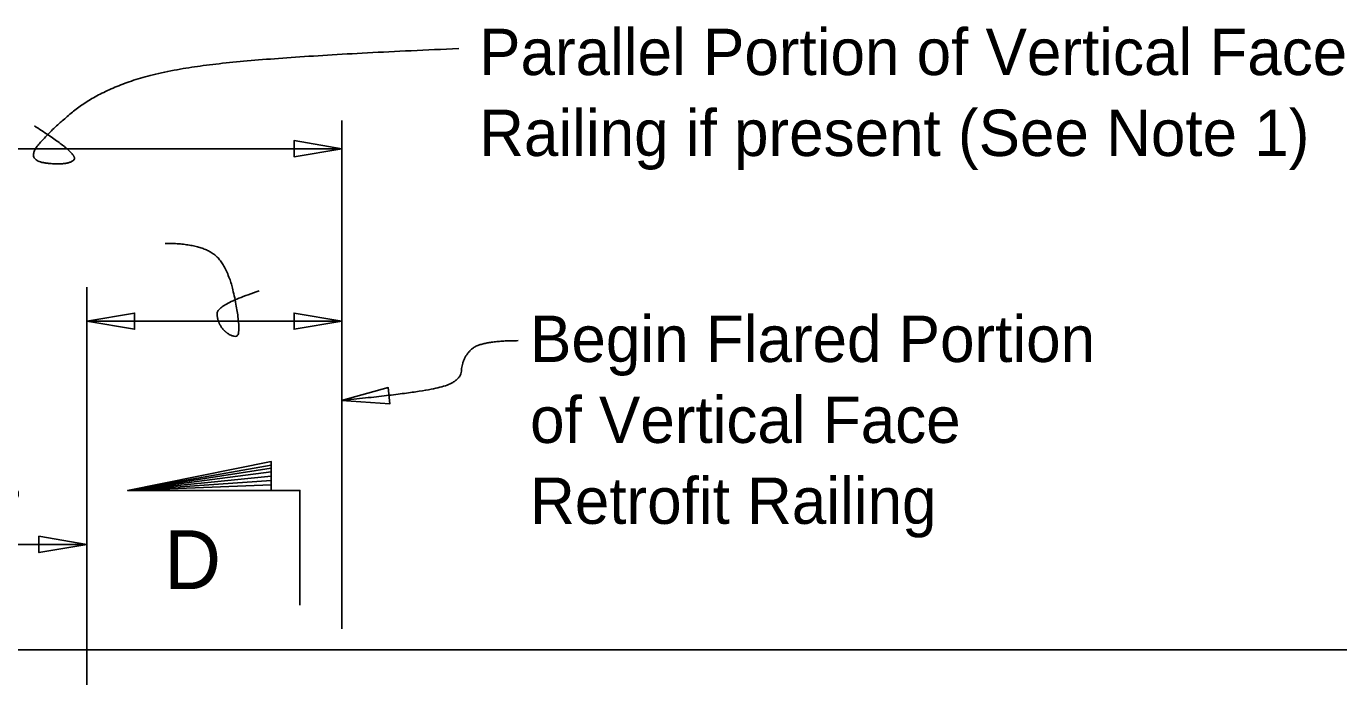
# Model space of a CAD drawing. Extents: x 1.5 to 68.7, y 0 to 31.1.
# Drawn here: x 28.44 to 34.15, y 13.67 to 16.53 of the extents above; entities that cross this region are included whole.
import ezdxf

# ---------------------------------------------------------------- set-up
doc = ezdxf.new("R2010")
doc.units = 0
for name, color, linetype in [('AdhocPoint_dp', 7, 'Continuous'), ('PlotBorder_dp', 7, 'Continuous'), ('SheetBorder_dp', 7, 'Continuous')]:
    doc.layers.add(name, color=color, linetype=linetype)

msp = doc.modelspace()

# ---------------------------------------------------------------- linework, layer by layer
at = {"layer": 'AdhocPoint_dp'}
for p, q in [((29.8106, 13.981), (29.8106, 16.1198)), ((29.8106, 16.0948), (29.8106, 13.9093)), ((28.7009, 13.6663), (28.7009, 15.3961)), ((29.8106, 15.2478), (28.7009, 15.2478)), ((28.878, 14.5119), (29.503, 14.6219)), ((29.503, 14.6085), (28.878, 14.5119)), ((28.878, 14.5119), (29.503, 14.5919)), ((29.503, 14.5735), (28.878, 14.5119)), ((28.878, 14.5119), (29.503, 14.5552)), ((29.503, 14.5352), (28.878, 14.5119))]:
    msp.add_line(p, q, dxfattribs=at)
for points in [[(26.2771, 15.9978), (29.8106, 15.9978)], [(29.628, 14.0119), (29.628, 14.5119), (28.878, 14.5119), (29.503, 14.6369), (29.503, 14.5119)]]:
    msp.add_lwpolyline(points, dxfattribs=at)
for points in [[(29.8106, 15.9978), (29.6024, 16.0331), (29.6024, 15.9626)], [(28.7009, 15.2478), (28.9091, 15.2126), (28.9091, 15.2831)], [(29.8106, 15.2478), (29.6024, 15.2831), (29.6024, 15.2126)], [(29.8085, 14.903), (30.0192, 14.8883), (30.0123, 14.9585)], [(28.7009, 14.2766), (28.4926, 14.3119), (28.4926, 14.2413)]]:
    msp.add_lwpolyline(points, close=True, dxfattribs=at)
for points in [[(30.3185, 16.4334), (29.7625, 16.41), (29.085, 16.3539), (28.7533, 16.2464), (28.5617, 16.0968), (28.4309, 15.9472), (28.6131, 15.9239), (28.6738, 15.9706), (28.4729, 16.0968)], [(29.0412, 15.5861), (29.189, 15.5861), (29.3172, 15.4924), (29.3763, 15.1816), (29.3221, 15.1816), (29.2679, 15.2408), (29.2679, 15.3197), (29.4502, 15.3789)], [(30.5774, 15.1629), (30.4111, 15.1629), (30.3332, 15.0849), (30.328, 14.9809), (30.1253, 14.9341), (29.8084, 14.903)], [(27.8361, 14.5528), (28.0726, 14.5528), (28.3289, 14.5528), (28.4472, 14.4862), (28.1022, 14.2766), (28.4398, 14.2766), (28.7009, 14.2766)]]:
    msp.add_open_spline(points, degree=2, dxfattribs=at)
at = {"layer": 'PlotBorder_dp'}
msp.add_line((36.5515, 13.8178), (26.2771, 13.8178), dxfattribs=at)

# ---------------------------------------------------------------- texts
at = {"layer": 'AdhocPoint_dp'}
for s, p in [('Parallel Portion of Vertical Face Retrofit ', (30.4075, 16.3181)), ('Railing if present (See Note 1)', (30.4075, 15.9661)), ('Begin Flared Portion ', (30.629, 15.0701)), ('of Vertical Face ', (30.629, 14.7181)), ('Retrofit Railing', (30.629, 14.3661))]:
    msp.add_text(s, height=0.2016, dxfattribs=at).set_placement(p)
at = {"layer": 'SheetBorder_dp'}
msp.add_text('D', height=0.256, dxfattribs=at).set_placement((29.0376, 14.0824))

doc.saveas('drawing.dxf')
